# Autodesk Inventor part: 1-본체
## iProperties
Created: 2015-03
Part Number: 1-본체
Document SubType Name: Modeling
Designer: now102
Density: 2.71 g/cm^3
Material: 알루미늄-6061
Mass: 450.78 g
Surface Area: 332.709 cm^2
Volume: 166.339 cm^3
Author: now102
